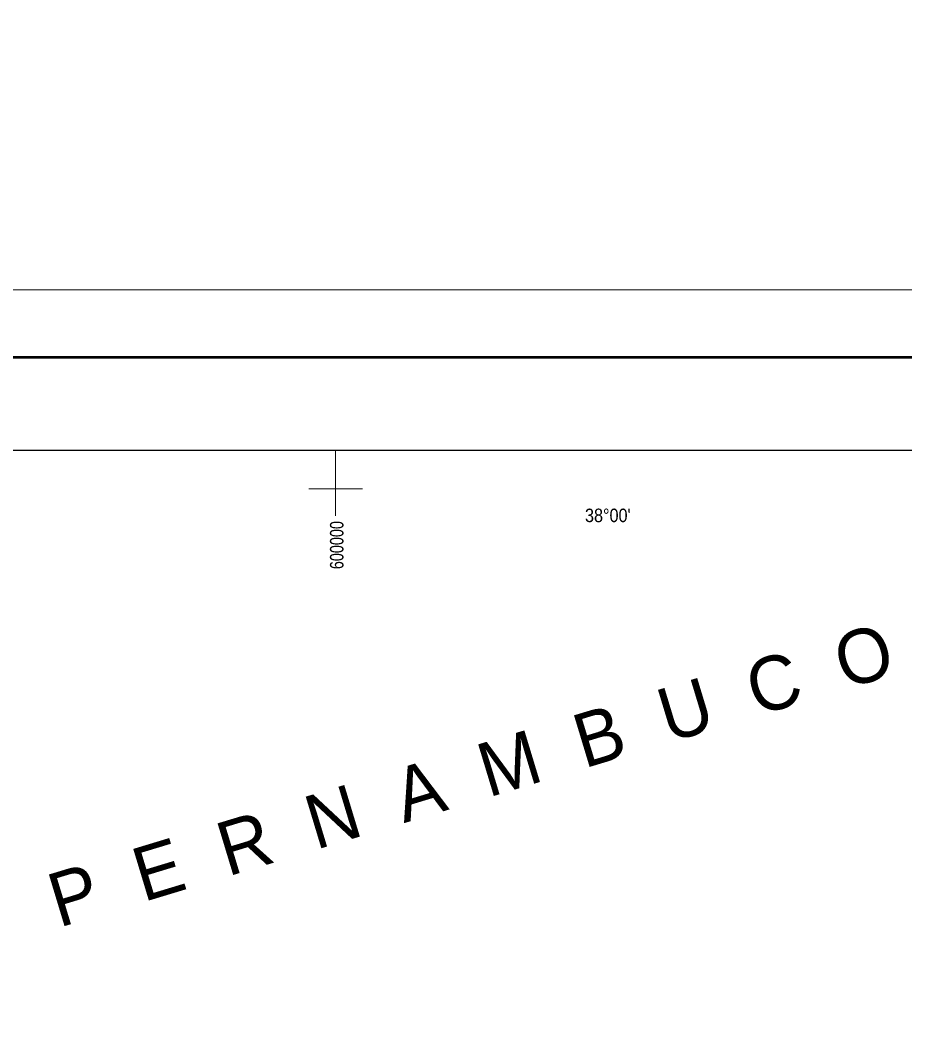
# Model space of a CAD drawing. Extents: x -1643653 to 4543381, y 1624270 to 13878484.
# Drawn here: x 588293 to 621123, y 9005087 to 9042389 of the extents above; entities that cross this region are included whole.
import ezdxf
from ezdxf.enums import TextEntityAlignment as Align

# ---------------------------------------------------------------- set-up
doc = ezdxf.new("R2010")
doc.units = 0
doc.header["$LTSCALE"] = 200
for name, color, linetype, lineweight in [('1', 7, 'Continuous', 13), ('2', 7, 'Continuous', 13), ('3', 7, 'Continuous', 13)]:
    doc.layers.add(name, color=color, linetype=linetype, lineweight=lineweight)
for name, color, linetype in [('42', 7, 'Continuous'), ('46', 7, 'Continuous'), ('47', 7, 'Continuous')]:
    doc.layers.add(name, color=color, linetype=linetype)

msp = doc.modelspace()

# ---------------------------------------------------------------- linework, layer by layer
at = {"layer": '1', "lineweight": 25}
msp.add_spline([(814781, 9009175.5), (814787.2, 9009173.4), (814796.9, 9009173.4), (814799.4, 9009172.4), (814805.1, 9009174.5), (814805.6, 9009176.5), (814811.7, 9009179.5), (814811.7, 9009179.5), (814801.5, 9009181), (814790.7, 9009181.5), (814784.1, 9009183.1), (814777.4, 9009185.1), (814778.4, 9009175.5)], degree=3, dxfattribs=at)
at = {"layer": '2'}
for p, q in [((600000, 9024000), (600000, 9026438.8)), ((599000, 9025000), (601000, 9025000))]:
    msp.add_line(p, q, dxfattribs=at)
at = {"layer": '3'}
msp.add_lwpolyline([(842807.3, 9032387.8), (842807.3, 8883887.8), (553961.7, 8883887.8), (553961.7, 9032387.8)], close=True, dxfattribs=at)
msp.add_lwpolyline([(842807.3, 9032387.8), (842807.3, 8883887.8), (553961.7, 8883887.8), (553961.7, 9032387.8)], close=True, dxfattribs=at)
at = {"layer": '3', "lineweight": 53}
msp.add_lwpolyline([(840307.3, 9029887.8), (840307.3, 8886387.8), (560211.7, 8886387.8), (560211.7, 9029887.8)], close=True, dxfattribs=at)
msp.add_lwpolyline([(840307.3, 9029887.8), (840307.3, 8886387.8), (560211.7, 8886387.8), (560211.7, 9029887.8)], close=True, dxfattribs=at)
at = {"layer": '3', "lineweight": 25}
msp.add_lwpolyline([(563033.9, 9026438.8), (793061.1, 9026438.8), (793495.6, 8889836.8), (563468.3, 8889836.8)], close=True, dxfattribs=at)

# ---------------------------------------------------------------- texts
at = {"layer": '42'}
msp.add_text('P  E  R  N  A  M  B  U  C  O', height=2000, rotation=16.855, dxfattribs=at).set_placement((589730.9, 9008723.5))
at = {"layer": '46', "width": 0.9}
msp.add_text("38°00'", height=500, dxfattribs=at).set_placement((610099.9, 9023770.4), align=Align.CENTER)
at = {"layer": '47', "width": 0.8}
msp.add_text('600000', height=500, rotation=90, dxfattribs=at).set_placement((600290.6, 9022917.4), align=Align.CENTER)

doc.saveas('drawing.dxf')
